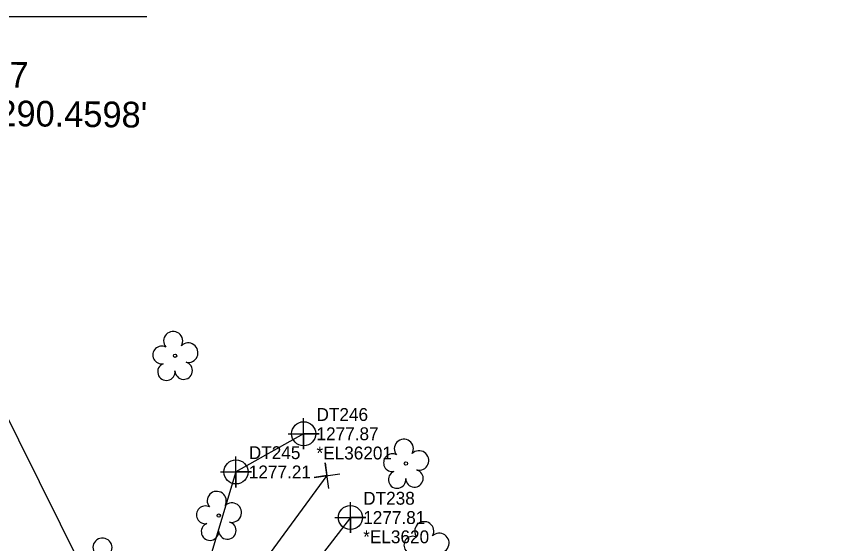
# Model space of a CAD drawing. Extents: x 1393723 to 1394549, y 957573 to 958412.
# Drawn here: x 1394117.7 to 1394278.6, y 958302.5 to 958405 of the extents above; entities that cross this region are included whole.
import ezdxf

# ---------------------------------------------------------------- set-up
doc = ezdxf.new("R2010")
doc.units = 0
for name, color, linetype in [('CTL Supplemental Horizontal and Vertical Text', 7, 'Continuous'), ('Default', 7, 'Continuous'), ('Exist Hydro Jurisdictional Stream or Body of Water', 7, 'Continuous'), ('Exist Hydro Stream or Body of Water Cogo Comment', 7, 'Continuous'), ('Exist Hydro Stream or Body of Water Cogo Elevation', 7, 'Continuous'), ('Exist Hydro Stream or Body of Water Cogo Number', 7, 'Continuous'), ('Exist Hydro Stream or Body of Water Cogo Point CELL', 7, 'Continuous'), ('Exist Property Corner CELL', 7, 'Continuous'), ('Exist Property Line', 7, 'Continuous'), ('Exist Right of Way Line', 7, 'Continuous'), ('Exist Roads EOP', 7, 'Continuous'), ('Exist Vegetation Tree CELL', 7, 'Continuous')]:
    doc.layers.add(name, color=color, linetype=linetype)

msp = doc.modelspace()

# ---------------------------------------------------------------- linework, layer by layer
at = {"layer": 'Default'}
msp.add_line((1394039.38, 958405.01), (1394143.05, 958405.01), dxfattribs=at)
at = {"layer": 'Exist Hydro Jurisdictional Stream or Body of Water'}
for points in [[(1394173.56, 958323.84), (1394160.39, 958316.41), (1394154.66, 958297.46), (1394149.27, 958283.15), (1394155.87, 958264.15), (1394168.98, 958246.06), (1394177.42, 958243.2), (1394198.48, 958248.51), (1394226.11, 958259.88), (1394245.4, 958262.42), (1394251.97, 958257.71), (1394253.55, 958252.43), (1394246.6, 958237.67), (1394241.52, 958222.95), (1394245.4, 958205.43), (1394258.52, 958177.52), (1394261.1, 958155.62), (1394254.7, 958129.06), (1394238.9, 958116.03), (1394219.59, 958103.52)], [(1394182.65, 958307.54), (1394169.76, 958290.8), (1394172.1, 958270.66), (1394177.6, 958260.63), (1394210.23, 958270.05), (1394243.43, 958275.21), (1394265.63, 958269.83), (1394275.6, 958257.19), (1394267.1, 958226.25), (1394278.61, 958197.12), (1394277.84, 958154), (1394270.52, 958123.51), (1394228.57, 958088.78)]]:
    msp.add_lwpolyline(points, dxfattribs=at)
at = {"layer": 'Exist Hydro Stream or Body of Water Cogo Point CELL'}
for points in [[(1394170.56, 958323.84), (1394176.56, 958323.84), (1394173.56, 958323.84), (1394173.56, 958320.84), (1394173.56, 958326.84)], [(1394157.39, 958316.41), (1394163.39, 958316.41), (1394160.39, 958316.41), (1394160.39, 958313.41), (1394160.39, 958319.41)], [(1394179.65, 958307.54), (1394185.65, 958307.54), (1394182.65, 958307.54), (1394182.65, 958304.54), (1394182.65, 958310.54)]]:
    msp.add_lwpolyline(points, dxfattribs=at)
for centre in [(1394173.56, 958323.84), (1394160.39, 958316.41), (1394182.65, 958307.54)]:
    msp.add_circle(centre, 2.34, dxfattribs=at)
at = {"layer": 'Exist Property Corner CELL'}
msp.add_line((1394178.1, 958315.69), (1394178.1, 958315.69), dxfattribs=at)
msp.add_lwpolyline([(1394178.48, 958313.22), (1394177.73, 958318.16), (1394178.1, 958315.69), (1394175.63, 958315.31), (1394180.58, 958316.06)], dxfattribs=at)
at = {"layer": 'Exist Property Line'}
msp.add_line((1394178.1, 958315.69), (1394162.21, 958294.13), dxfattribs=at)
at = {"layer": 'Exist Right of Way Line'}
msp.add_line((1394113.29, 958332.2), (1394126.16, 958306.31), dxfattribs=at)
msp.add_arc((1396069.16, 959272.56), 2170, 206.44093, 210.98819, dxfattribs=at)
at = {"layer": 'Exist Roads EOP'}
for points in [[(1394096.21, 958320.22), (1394117.22, 958277.69), (1394140.09, 958234.47), (1394160.7, 958197.15), (1394182.74, 958159.12)], [(1394078.9, 958312.9), (1394101.02, 958268.7), (1394123.33, 958225.72), (1394144.25, 958188.59), (1394165.82, 958150.9)]]:
    msp.add_spline(points, degree=3, dxfattribs=at)
at = {"layer": 'Exist Vegetation Tree CELL'}
for p, q in [((1394148.55, 958339.02), (1394148.55, 958339.02)), ((1394193.45, 958318.05), (1394193.45, 958318.05)), ((1394157.03, 958307.91), (1394157.03, 958307.91))]:
    msp.add_line(p, q, dxfattribs=at)
for centre in [(1394148.55, 958339.02), (1394193.45, 958318.05), (1394157.03, 958307.91)]:
    msp.add_circle(centre, 0.326, dxfattribs=at)
for centre, radius, start, end in [((1394148.16, 958341.89), 1.86, 330.1651, 219.7134), ((1394145.94, 958339.17), 1.73, 62.6636, 279.3457), ((1394151.1, 958339.61), 1.9, 257.1011, 134.1999), ((1394150.22, 958336.12), 1.7, 181.2822, 74.56), ((1394146.84, 958335.9), 1.69, 111.5671, 6.231), ((1394193.06, 958320.92), 1.86, 330.1651, 219.7134), ((1394190.84, 958318.2), 1.73, 62.6636, 279.3457), ((1394196, 958318.63), 1.9, 257.1011, 134.1999), ((1394195.12, 958315.15), 1.7, 181.2822, 74.56), ((1394191.74, 958314.92), 1.69, 111.5671, 6.231), ((1394156.65, 958310.78), 1.86, 330.1651, 219.7134), ((1394159.58, 958308.5), 1.9, 257.1011, 134.1999), ((1394154.43, 958308.06), 1.73, 62.6636, 279.3457), ((1394155.33, 958304.79), 1.69, 111.5671, 6.231), ((1394158.71, 958305.01), 1.7, 181.2822, 74.56), ((1394197.03, 958304.88), 1.86, 330.1651, 219.7134), ((1394194.81, 958302.16), 1.73, 62.6636, 279.3457), ((1394199.96, 958302.59), 1.9, 257.1011, 134.1999), ((1394134.41, 958301.69), 1.86, 330.1651, 219.7134)]:
    msp.add_arc(centre, radius, start, end, dxfattribs=at)

# ---------------------------------------------------------------- texts
at = {"layer": 'CTL Supplemental Horizontal and Vertical Text'}
for s, p in [('E = 1394030.8537', (1394065.14, 958391.7)), ("ELEVATION = 1290.4598' ", (1394065.07, 958384.2))]:
    msp.add_text(s, height=5, rotation=359.4089, dxfattribs=at).set_placement(p)
at = {"layer": 'Exist Hydro Stream or Body of Water Cogo Comment'}
for s, p in [('*EL36201', (1394176.06, 958318.84)), ('*EL3620', (1394185.15, 958302.54))]:
    msp.add_text(s, height=2.5, dxfattribs=at).set_placement(p)
at = {"layer": 'Exist Hydro Stream or Body of Water Cogo Elevation'}
for s, p in [('1277.87', (1394176.06, 958322.59)), ('1277.21', (1394162.89, 958315.16)), ('1277.81', (1394185.15, 958306.29))]:
    msp.add_text(s, height=2.5, dxfattribs=at).set_placement(p)
at = {"layer": 'Exist Hydro Stream or Body of Water Cogo Number'}
for s, p in [('DT246', (1394176.06, 958326.34)), ('DT245', (1394162.89, 958318.91)), ('DT238', (1394185.15, 958310.04))]:
    msp.add_text(s, height=2.5, dxfattribs=at).set_placement(p)

doc.saveas('drawing.dxf')
